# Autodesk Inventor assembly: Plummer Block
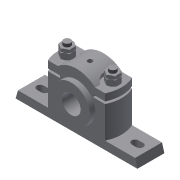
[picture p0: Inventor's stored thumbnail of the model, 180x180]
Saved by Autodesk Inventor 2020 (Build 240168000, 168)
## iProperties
Created: 2011-07
Part Number: Plummer Block
Document SubType Name: Assembly
Designer: CadCim
Author: CadCim
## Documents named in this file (7)
- D:\Autodesk Inventor_2020\Resources\Resources\Inventor_2020_tut\Inventor_2020_tut\c09_Inv_2020_tut\c09_Inv_tut_2020\c09_tut02_inv\Plummer Block\Plummer Block.iam
- D:\Autodesk Inventor_2020\Resources\Resources\Inventor_2020_tut\Inventor_2020_tut\c09_Inv_2020_tut\c09_Inv_tut_2020\c09_tut02_inv\Plummer Block\Casting.ipt
- D:\Autodesk Inventor_2020\Resources\Resources\Inventor_2020_tut\Inventor_2020_tut\c09_Inv_2020_tut\c09_Inv_tut_2020\c09_tut02_inv\Plummer Block\Brasses.ipt
- D:\Autodesk Inventor_2020\Resources\Resources\Inventor_2020_tut\Inventor_2020_tut\c09_Inv_2020_tut\c09_Inv_tut_2020\c09_tut02_inv\Plummer Block\Cap.ipt
- D:\Autodesk Inventor_2020\Resources\Resources\Inventor_2020_tut\Inventor_2020_tut\c09_Inv_2020_tut\c09_Inv_tut_2020\c09_tut02_inv\Plummer Block\Bolt.ipt
- D:\Autodesk Inventor_2020\Resources\Resources\Inventor_2020_tut\Inventor_2020_tut\c09_Inv_2020_tut\c09_Inv_tut_2020\c09_tut02_inv\Plummer Block\Nut.ipt
- D:\Autodesk Inventor_2020\Resources\Resources\Inventor_2020_tut\Inventor_2020_tut\c09_Inv_2020_tut\c09_Inv_tut_2020\c09_tut02_inv\Plummer Block\locknut.ipt
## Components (9 placed, 6 different names)
1. Casting:1 — Mate:1, Mate:2, Insert:1, Angle:1, Insert:2, Angle:2
2. Brasses:1 — Mate:1, Mate:2, Mate:3, Mate:4
3. Cap:1 — Mate:3, Mate:4, Insert:3, Insert:4
4. Bolt:1 — Insert:1, Angle:1
5. Bolt:2 — Insert:2, Angle:2
6. Nut.:4 — Insert:3, Insert:5, Angle:4
7. Nut.:5 — Insert:4, Insert:6, Angle:3
8. locknut:1 — Insert:5, Angle:4
9. locknut:2 — Insert:6, Angle:3
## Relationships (14: Insert 6, Mate 4, Angle 4)
- Mate:1: Casting:1 ↔ Brasses:1
- Mate:2: Casting:1 ↔ Brasses:1
- Mate:3: Brasses:1 ↔ Cap:1
- Mate:4: Brasses:1 ↔ Cap:1
- Insert:1: Casting:1 ↔ Bolt:1
- Angle:1: Casting:1 ↔ Bolt:1
- Insert:2: Casting:1 ↔ Bolt:2
- Angle:2: Casting:1 ↔ Bolt:2
- Insert:3: Cap:1 ↔ Nut.:4
- Insert:4: Cap:1 ↔ Nut.:5
- Insert:5: Nut.:4 ↔ locknut:1
- Insert:6: Nut.:5 ↔ locknut:2
- Angle:3: Nut.:5 ↔ locknut:2
- Angle:4: Nut.:4 ↔ locknut:1
